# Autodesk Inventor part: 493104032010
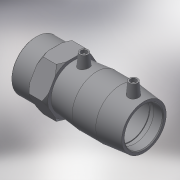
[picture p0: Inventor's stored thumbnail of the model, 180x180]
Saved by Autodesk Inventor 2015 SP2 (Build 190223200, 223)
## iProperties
Created: 2017-06
Part Number: 493104032010
Material: Generic
Description: PLASSON FEMALE TRANSITION COUPLER 32-1"
Document SubType Name: Modeling
Designer: KIM
Mass: 101.253 g
Surface Area: 309.495 cm^2
Volume: 101.253 cm^3
Density: 1 g/cm^3
Appearance: Default
Author: KIM
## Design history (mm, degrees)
derived "493104.ipt"
feature "Solid1::493104.ipt"
tag "TaggingFeature1"
body "Solid1"
other parameters: "d0" = 88, "d1" = 32, "d2" = 44, "d3" = 42, "d4" = 29.33333, "d5" = 39.6, "d6" = 30.4, "d7" = 32, "d8" = 168 deg, "d10" = 16.8, "d11" = 5.6, "d29" = 42, "d30" = 14, "d31" = 30.8, "d34" = 5 deg, "d41" = 4, "d42" = 14, "d43" = 0, "d48" = 3, "d49" = 0, "d55" = 25, "d57" = 23, "d59" = 30.291, "d60" = 22.5, "d70" = 44, "d71" = 12.5, "d72" = 0, "d73" = 45 deg, "d74" = 2.3, "d75" = 45 deg, "d77" = 0.48, "d80" = 0.64, "d_" = 32, "L_" = 113, "L_1" = 42, "D_1" = 44, "A_" = 42, "d_2" = 12, "L_2" = 25, "D_" = 23, "R_p" = 30.291
